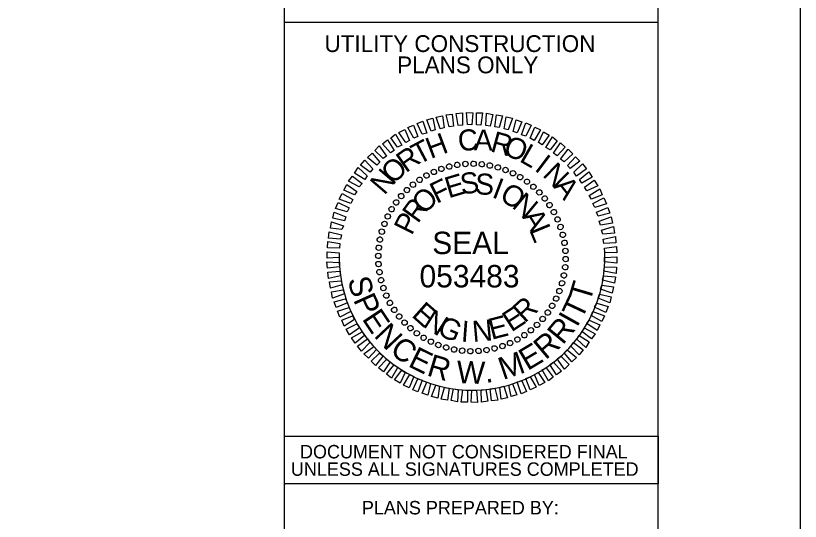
# Model space of a CAD drawing. Extents: x 2787886 to 2789612, y 1113277 to 1114394.
# Drawn here: x 2789401.8 to 2789611.8, y 1114118.8 to 1114254.2 of the extents above; entities that cross this region are included whole.
import ezdxf

# ---------------------------------------------------------------- set-up
doc = ezdxf.new("R2010")
doc.units = 0
for name, color, linetype in [('Scratch_Level_0', 7, 'Continuous'), ('Sheet PE Seal CELL', 7, 'Continuous'), ('Sheet Plan CELL', 7, 'Continuous'), ('Sheet_Data_Field_CELL', 7, 'Continuous'), ('Sheet_Plan_And_Profile_CELL', 7, 'Continuous'), ('Sheet_Plot_Border_Outside_CELL', 7, 'Continuous')]:
    doc.layers.add(name, color=color, linetype=linetype)

msp = doc.modelspace()

# ---------------------------------------------------------------- linework, layer by layer
at = {"layer": 'Scratch_Level_0'}
msp.add_arc((2789523.92, 1114189.47), 35.54, 180.0118, 2.0847, dxfattribs=at)
at = {"layer": 'Sheet PE Seal CELL'}
for p, q in [((2789515.68, 1114213.21), (2789515.68, 1114213.21)), ((2789517.78, 1114213.81), (2789517.78, 1114213.81)), ((2789519.98, 1114214.21), (2789519.98, 1114214.21)), ((2789522.13, 1114214.51), (2789522.13, 1114214.51)), ((2789524.33, 1114214.56), (2789524.33, 1114214.56)), ((2789526.53, 1114214.41), (2789526.53, 1114214.41)), ((2789528.68, 1114214.06), (2789528.68, 1114214.06)), ((2789530.78, 1114213.61), (2789530.78, 1114213.61)), ((2789532.88, 1114212.91), (2789532.88, 1114212.91)), ((2789511.73, 1114211.41), (2789511.73, 1114211.41)), ((2789513.68, 1114212.41), (2789513.68, 1114212.41)), ((2789534.88, 1114212.01), (2789534.88, 1114212.01)), ((2789536.83, 1114211.01), (2789536.83, 1114211.01)), ((2789508.08, 1114209.01), (2789508.08, 1114209.01)), ((2789509.83, 1114210.26), (2789509.83, 1114210.26)), ((2789538.63, 1114209.76), (2789538.63, 1114209.76)), ((2789540.38, 1114208.41), (2789540.38, 1114208.41)), ((2789506.43, 1114207.51), (2789506.43, 1114207.51)), ((2789541.93, 1114206.91), (2789541.93, 1114206.91)), ((2789503.58, 1114204.21), (2789503.58, 1114204.21)), ((2789504.93, 1114205.96), (2789504.93, 1114205.96)), ((2789543.43, 1114205.26), (2789543.43, 1114205.26)), ((2789502.33, 1114202.41), (2789502.33, 1114202.41)), ((2789544.68, 1114203.51), (2789544.68, 1114203.51)), ((2789501.33, 1114200.46), (2789501.33, 1114200.46)), ((2789545.83, 1114201.61), (2789545.83, 1114201.61)), ((2789500.43, 1114198.46), (2789500.43, 1114198.46)), ((2789546.83, 1114199.66), (2789546.83, 1114199.66)), ((2789499.73, 1114196.36), (2789499.73, 1114196.36)), ((2789547.63, 1114197.66), (2789547.63, 1114197.66)), ((2789499.28, 1114194.26), (2789499.28, 1114194.26)), ((2789548.23, 1114195.56), (2789548.23, 1114195.56)), ((2789498.93, 1114192.11), (2789498.93, 1114192.11)), ((2789548.63, 1114193.36), (2789548.63, 1114193.36)), ((2789498.78, 1114189.91), (2789498.78, 1114189.91)), ((2789523.88, 1114189.46), (2789523.88, 1114189.46)), ((2789548.93, 1114191.21), (2789548.93, 1114191.21)), ((2789498.83, 1114187.71), (2789498.83, 1114187.71)), ((2789548.98, 1114189.01), (2789548.98, 1114189.01)), ((2789499.13, 1114185.56), (2789499.13, 1114185.56)), ((2789548.83, 1114186.81), (2789548.83, 1114186.81)), ((2789499.53, 1114183.36), (2789499.53, 1114183.36)), ((2789548.48, 1114184.66), (2789548.48, 1114184.66)), ((2789500.13, 1114181.26), (2789500.13, 1114181.26)), ((2789548.03, 1114182.56), (2789548.03, 1114182.56)), ((2789500.93, 1114179.26), (2789500.93, 1114179.26)), ((2789547.33, 1114180.46), (2789547.33, 1114180.46)), ((2789501.93, 1114177.31), (2789501.93, 1114177.31)), ((2789546.43, 1114178.46), (2789546.43, 1114178.46)), ((2789503.08, 1114175.41), (2789503.08, 1114175.41)), ((2789545.43, 1114176.51), (2789545.43, 1114176.51)), ((2789504.33, 1114173.66), (2789504.33, 1114173.66)), ((2789542.83, 1114172.96), (2789542.83, 1114172.96)), ((2789544.18, 1114174.71), (2789544.18, 1114174.71)), ((2789505.83, 1114172.01), (2789505.83, 1114172.01)), ((2789541.33, 1114171.41), (2789541.33, 1114171.41)), ((2789507.38, 1114170.51), (2789507.38, 1114170.51)), ((2789509.13, 1114169.16), (2789509.13, 1114169.16)), ((2789537.93, 1114168.66), (2789537.93, 1114168.66)), ((2789539.68, 1114169.91), (2789539.68, 1114169.91)), ((2789510.93, 1114167.91), (2789510.93, 1114167.91)), ((2789512.88, 1114166.91), (2789512.88, 1114166.91)), ((2789534.08, 1114166.51), (2789534.08, 1114166.51)), ((2789536.03, 1114167.51), (2789536.03, 1114167.51)), ((2789514.88, 1114166.01), (2789514.88, 1114166.01)), ((2789516.98, 1114165.31), (2789516.98, 1114165.31)), ((2789519.08, 1114164.86), (2789519.08, 1114164.86)), ((2789521.23, 1114164.51), (2789521.23, 1114164.51)), ((2789523.43, 1114164.36), (2789523.43, 1114164.36)), ((2789525.63, 1114164.41), (2789525.63, 1114164.41)), ((2789527.78, 1114164.71), (2789527.78, 1114164.71)), ((2789529.98, 1114165.11), (2789529.98, 1114165.11)), ((2789532.08, 1114165.71), (2789532.08, 1114165.71))]:
    msp.add_line(p, q, dxfattribs=at)
for points in [[(2789515.38, 1114223.91), (2789514.33, 1114227.06), (2789516.03, 1114227.41), (2789516.43, 1114224.16)], [(2789517.78, 1114224.46), (2789516.98, 1114227.66), (2789518.63, 1114227.81), (2789518.98, 1114224.61)], [(2789520.18, 1114224.76), (2789519.63, 1114227.96), (2789521.33, 1114228.16), (2789521.38, 1114224.91)], [(2789522.68, 1114225.01), (2789522.43, 1114228.26), (2789524.08, 1114228.21), (2789523.88, 1114224.96)], [(2789525.08, 1114224.96), (2789525.08, 1114228.21), (2789526.73, 1114228.16), (2789526.28, 1114224.91)], [(2789527.58, 1114224.81), (2789527.78, 1114228.06), (2789529.43, 1114227.76), (2789528.78, 1114224.61)], [(2789529.98, 1114224.41), (2789530.43, 1114227.61), (2789532.08, 1114227.36), (2789531.18, 1114224.26)], [(2789510.53, 1114222.46), (2789509.23, 1114225.36), (2789510.73, 1114225.96), (2789511.78, 1114222.76)], [(2789512.98, 1114223.26), (2789511.83, 1114226.26), (2789513.38, 1114226.71), (2789514.03, 1114223.61)], [(2789532.53, 1114223.86), (2789533.03, 1114227.11), (2789534.73, 1114226.71), (2789533.58, 1114223.61)], [(2789534.93, 1114223.21), (2789535.68, 1114226.31), (2789537.23, 1114225.81), (2789535.98, 1114222.86)], [(2789537.18, 1114222.31), (2789538.33, 1114225.46), (2789539.73, 1114224.86), (2789538.33, 1114221.96)], [(2789506.18, 1114220.21), (2789504.33, 1114222.91), (2789505.88, 1114223.71), (2789507.13, 1114220.81)], [(2789508.33, 1114221.41), (2789506.73, 1114224.21), (2789508.28, 1114224.91), (2789509.43, 1114221.86)], [(2789539.43, 1114221.36), (2789540.68, 1114224.31), (2789542.23, 1114223.61), (2789540.53, 1114220.81)], [(2789541.73, 1114220.21), (2789543.08, 1114223.06), (2789544.58, 1114222.21), (2789542.68, 1114219.61)], [(2789503.98, 1114218.96), (2789502.13, 1114221.51), (2789503.43, 1114222.46), (2789505.08, 1114219.56)], [(2789543.68, 1114218.86), (2789545.43, 1114221.76), (2789546.73, 1114220.71), (2789544.78, 1114218.26)], [(2789500.08, 1114215.91), (2789497.88, 1114218.11), (2789499.08, 1114219.31), (2789501.03, 1114216.61)], [(2789502.08, 1114217.46), (2789499.93, 1114219.86), (2789501.28, 1114220.91), (2789503.03, 1114218.11)], [(2789545.73, 1114217.36), (2789547.58, 1114220.11), (2789548.88, 1114219.01), (2789546.68, 1114216.66)], [(2789498.43, 1114214.16), (2789495.88, 1114216.21), (2789497.13, 1114217.36), (2789499.23, 1114214.96)], [(2789547.63, 1114215.81), (2789549.68, 1114218.41), (2789550.88, 1114217.21), (2789548.58, 1114215.06)], [(2789496.68, 1114212.26), (2789494.08, 1114214.21), (2789495.18, 1114215.51), (2789497.38, 1114213.16)], [(2789549.43, 1114214.06), (2789551.58, 1114216.41), (2789552.78, 1114215.21), (2789550.18, 1114213.26)], [(2789495.18, 1114210.36), (2789492.48, 1114212.06), (2789493.43, 1114213.51), (2789495.83, 1114211.31)], [(2789551.18, 1114212.26), (2789553.48, 1114214.51), (2789554.53, 1114213.16), (2789551.88, 1114211.26)], [(2789493.68, 1114208.36), (2789490.88, 1114209.86), (2789491.88, 1114211.26), (2789494.48, 1114209.26)], [(2789552.68, 1114210.31), (2789555.13, 1114212.41), (2789556.08, 1114210.96), (2789553.28, 1114209.36)], [(2789492.48, 1114206.21), (2789489.63, 1114207.46), (2789490.38, 1114209.01), (2789493.08, 1114207.16)], [(2789553.98, 1114208.26), (2789556.63, 1114210.16), (2789557.58, 1114208.66), (2789554.68, 1114207.26)], [(2789491.48, 1114203.91), (2789488.38, 1114205.06), (2789489.13, 1114206.61), (2789491.98, 1114205.01)], [(2789555.28, 1114206.06), (2789558.08, 1114207.81), (2789558.73, 1114206.26), (2789555.88, 1114205.11)], [(2789490.48, 1114201.71), (2789487.38, 1114202.61), (2789488.03, 1114204.16), (2789491.03, 1114202.76)], [(2789556.28, 1114203.91), (2789559.23, 1114205.41), (2789559.88, 1114203.81), (2789556.78, 1114202.81)], [(2789557.18, 1114201.56), (2789560.23, 1114202.86), (2789560.78, 1114201.31), (2789557.68, 1114200.51)], [(2789489.73, 1114199.31), (2789486.63, 1114199.96), (2789486.98, 1114201.61), (2789490.13, 1114200.36)], [(2789557.98, 1114199.16), (2789561.18, 1114200.31), (2789561.48, 1114198.66), (2789558.33, 1114198.11)], [(2789489.08, 1114196.91), (2789485.98, 1114197.31), (2789486.33, 1114199.01), (2789489.48, 1114197.96)], [(2789488.68, 1114194.36), (2789485.48, 1114194.66), (2789485.68, 1114196.36), (2789488.93, 1114195.56)], [(2789558.58, 1114196.76), (2789561.73, 1114197.71), (2789562.03, 1114196.01), (2789558.88, 1114195.71)], [(2789488.43, 1114191.96), (2789485.18, 1114192.06), (2789485.28, 1114193.71), (2789488.53, 1114193.16)], [(2789559.03, 1114194.36), (2789562.28, 1114195.06), (2789562.43, 1114193.36), (2789559.23, 1114193.16)], [(2789559.33, 1114191.96), (2789562.58, 1114192.36), (2789562.68, 1114190.66), (2789559.43, 1114190.76)], [(2789488.38, 1114189.46), (2789485.13, 1114189.31), (2789485.13, 1114191.01), (2789488.38, 1114190.66)], [(2789559.38, 1114189.46), (2789562.63, 1114189.61), (2789562.63, 1114187.91), (2789559.38, 1114188.26)], [(2789488.43, 1114186.96), (2789485.18, 1114186.56), (2789485.08, 1114188.26), (2789488.33, 1114188.16)], [(2789488.73, 1114184.56), (2789485.48, 1114183.86), (2789485.33, 1114185.56), (2789488.53, 1114185.76)], [(2789559.33, 1114186.96), (2789562.58, 1114186.86), (2789562.48, 1114185.21), (2789559.23, 1114185.76)], [(2789489.18, 1114182.16), (2789486.03, 1114181.21), (2789485.73, 1114182.91), (2789488.88, 1114183.21)], [(2789559.08, 1114184.56), (2789562.28, 1114184.26), (2789562.08, 1114182.56), (2789558.83, 1114183.36)], [(2789558.68, 1114182.01), (2789561.78, 1114181.61), (2789561.43, 1114179.91), (2789558.28, 1114180.96)], [(2789489.78, 1114179.76), (2789486.58, 1114178.61), (2789486.28, 1114180.26), (2789489.43, 1114180.81)], [(2789558.03, 1114179.61), (2789561.13, 1114178.96), (2789560.78, 1114177.31), (2789557.63, 1114178.56)], [(2789490.58, 1114177.36), (2789487.53, 1114176.06), (2789486.98, 1114177.61), (2789490.08, 1114178.41)], [(2789557.28, 1114177.21), (2789560.38, 1114176.31), (2789559.73, 1114174.76), (2789556.73, 1114176.16)], [(2789491.48, 1114175.01), (2789488.53, 1114173.51), (2789487.88, 1114175.11), (2789490.98, 1114176.11)], [(2789556.28, 1114175.01), (2789559.38, 1114173.86), (2789558.63, 1114172.31), (2789555.78, 1114173.91)], [(2789492.48, 1114172.86), (2789489.68, 1114171.11), (2789489.03, 1114172.66), (2789491.88, 1114173.81)], [(2789555.28, 1114172.71), (2789558.13, 1114171.46), (2789557.38, 1114169.91), (2789554.68, 1114171.76)], [(2789493.78, 1114170.66), (2789491.13, 1114168.76), (2789490.18, 1114170.26), (2789493.08, 1114171.66)], [(2789554.08, 1114170.56), (2789556.88, 1114169.06), (2789555.88, 1114167.66), (2789553.28, 1114169.66)], [(2789495.08, 1114168.61), (2789492.63, 1114166.51), (2789491.68, 1114167.96), (2789494.48, 1114169.56)], [(2789552.58, 1114168.56), (2789555.28, 1114166.86), (2789554.33, 1114165.41), (2789551.93, 1114167.61)], [(2789496.58, 1114166.66), (2789494.28, 1114164.41), (2789493.23, 1114165.76), (2789495.88, 1114167.66)], [(2789551.08, 1114166.66), (2789553.68, 1114164.71), (2789552.58, 1114163.41), (2789550.38, 1114165.76)], [(2789498.33, 1114164.86), (2789496.18, 1114162.51), (2789494.98, 1114163.71), (2789497.58, 1114165.66)], [(2789549.33, 1114164.76), (2789551.88, 1114162.71), (2789550.63, 1114161.56), (2789548.53, 1114163.96)], [(2789500.13, 1114163.11), (2789498.08, 1114160.51), (2789496.88, 1114161.71), (2789499.18, 1114163.86)], [(2789502.03, 1114161.56), (2789500.18, 1114158.81), (2789498.88, 1114159.91), (2789501.08, 1114162.26)], [(2789547.68, 1114163.01), (2789549.88, 1114160.81), (2789548.68, 1114159.61), (2789546.73, 1114162.31)], [(2789504.08, 1114160.06), (2789502.33, 1114157.16), (2789501.03, 1114158.21), (2789502.98, 1114160.66)], [(2789545.68, 1114161.46), (2789547.83, 1114159.06), (2789546.48, 1114158.01), (2789544.73, 1114160.81)], [(2789506.03, 1114158.71), (2789504.68, 1114155.86), (2789503.18, 1114156.71), (2789505.08, 1114159.31)], [(2789508.33, 1114157.56), (2789507.08, 1114154.61), (2789505.53, 1114155.31), (2789507.23, 1114158.11)], [(2789541.58, 1114158.71), (2789543.43, 1114156.01), (2789541.88, 1114155.21), (2789540.63, 1114158.11)], [(2789543.78, 1114159.96), (2789545.63, 1114157.41), (2789544.33, 1114156.46), (2789542.68, 1114159.36)], [(2789510.58, 1114156.61), (2789509.43, 1114153.46), (2789508.03, 1114154.06), (2789509.43, 1114156.96)], [(2789512.83, 1114155.71), (2789512.08, 1114152.61), (2789510.53, 1114153.11), (2789511.78, 1114156.06)], [(2789537.23, 1114156.46), (2789538.53, 1114153.56), (2789537.03, 1114152.96), (2789535.98, 1114156.16)], [(2789539.43, 1114157.51), (2789541.03, 1114154.71), (2789539.48, 1114154.01), (2789538.33, 1114157.06)], [(2789515.23, 1114155.06), (2789514.73, 1114151.81), (2789513.03, 1114152.21), (2789514.18, 1114155.31)], [(2789517.78, 1114154.51), (2789517.33, 1114151.31), (2789515.68, 1114151.56), (2789516.58, 1114154.66)], [(2789520.18, 1114154.11), (2789519.98, 1114150.86), (2789518.33, 1114151.16), (2789518.98, 1114154.31)], [(2789522.68, 1114153.96), (2789522.68, 1114150.71), (2789521.03, 1114150.76), (2789521.48, 1114154.01)], [(2789525.08, 1114153.91), (2789525.33, 1114150.66), (2789523.68, 1114150.71), (2789523.88, 1114153.96)], [(2789527.58, 1114154.16), (2789528.13, 1114150.96), (2789526.43, 1114150.76), (2789526.38, 1114154.01)], [(2789529.98, 1114154.46), (2789530.78, 1114151.26), (2789529.13, 1114151.11), (2789528.78, 1114154.31)], [(2789532.38, 1114155.01), (2789533.43, 1114151.86), (2789531.73, 1114151.51), (2789531.33, 1114154.76)], [(2789534.78, 1114155.66), (2789535.93, 1114152.66), (2789534.38, 1114152.21), (2789533.73, 1114155.31)]]:
    msp.add_lwpolyline(points, close=True, dxfattribs=at)
for centre, major_axis in [((2789519.96, 1114214.23), (-0.113, 0.711)), ((2789522.13, 1114214.48), (-0.05, 0.718)), ((2789524.32, 1114214.53), (0.013, 0.72)), ((2789526.5, 1114214.4), (0.075, 0.716)), ((2789528.67, 1114214.08), (0.137, 0.707)), ((2789513.68, 1114212.37), (-0.293, 0.658)), ((2789515.71, 1114213.17), (-0.234, 0.681)), ((2789517.81, 1114213.79), (-0.174, 0.699)), ((2789530.79, 1114213.57), (0.198, 0.692)), ((2789532.87, 1114212.87), (0.258, 0.672)), ((2789534.87, 1114212), (0.316, 0.647)), ((2789509.86, 1114210.25), (-0.403, 0.597)), ((2789511.72, 1114211.39), (-0.349, 0.63)), ((2789536.8, 1114210.96), (0.371, 0.617)), ((2789538.62, 1114209.75), (0.423, 0.582)), ((2789508.1, 1114208.95), (-0.453, 0.56)), ((2789540.33, 1114208.39), (0.472, 0.543)), ((2789504.95, 1114205.91), (-0.543, 0.472)), ((2789506.46, 1114207.5), (-0.5, 0.518)), ((2789541.92, 1114206.88), (0.518, 0.5)), ((2789503.59, 1114204.2), (-0.582, 0.423)), ((2789543.37, 1114205.24), (0.56, 0.453)), ((2789544.67, 1114203.48), (0.597, 0.403)), ((2789502.38, 1114202.38), (-0.617, 0.371)), ((2789545.82, 1114201.62), (0.63, 0.349)), ((2789501.34, 1114200.45), (-0.647, 0.316)), ((2789546.79, 1114199.66), (0.658, 0.293)), ((2789500.47, 1114198.45), (-0.672, 0.258)), ((2789547.59, 1114197.62), (0.681, 0.234)), ((2789499.77, 1114196.37), (-0.692, 0.198)), ((2789548.22, 1114195.53), (0.699, 0.174)), ((2789499.26, 1114194.24), (-0.707, 0.137)), ((2789548.65, 1114193.38), (0.711, 0.113)), ((2789498.94, 1114192.08), (-0.716, 0.075)), ((2789548.9, 1114191.21), (0.718, 0.05)), ((2789498.8, 1114189.9), (-0.72, 0.013)), ((2789548.96, 1114189.02), (0.72, -0.013)), ((2789498.86, 1114187.71), (-0.718, -0.05)), ((2789548.82, 1114186.84), (0.716, -0.075)), ((2789499.11, 1114185.54), (-0.711, -0.113)), ((2789548.5, 1114184.67), (0.707, -0.137)), ((2789499.55, 1114183.39), (-0.699, -0.174)), ((2789547.99, 1114182.55), (0.692, -0.198)), ((2789500.17, 1114181.29), (-0.681, -0.234)), ((2789547.29, 1114180.47), (0.672, -0.258)), ((2789500.97, 1114179.26), (-0.658, -0.293)), ((2789546.42, 1114178.46), (0.647, -0.316)), ((2789501.94, 1114177.3), (-0.63, -0.349)), ((2789545.38, 1114176.54), (0.617, -0.371)), ((2789503.09, 1114175.43), (-0.597, -0.403)), ((2789544.17, 1114174.72), (0.582, -0.423)), ((2789504.39, 1114173.68), (-0.56, -0.453)), ((2789505.84, 1114172.04), (-0.518, -0.5)), ((2789542.81, 1114173), (0.543, -0.472)), ((2789507.43, 1114170.53), (-0.472, -0.543)), ((2789539.66, 1114169.97), (0.453, -0.56)), ((2789541.3, 1114171.42), (0.5, -0.518)), ((2789509.14, 1114169.17), (-0.423, -0.582)), ((2789510.96, 1114167.96), (-0.371, -0.617)), ((2789537.9, 1114168.67), (0.403, -0.597)), ((2789512.89, 1114166.92), (-0.316, -0.647)), ((2789514.89, 1114166.04), (-0.258, -0.672)), ((2789532.05, 1114165.75), (0.234, -0.681)), ((2789534.08, 1114166.55), (0.293, -0.658)), ((2789536.04, 1114167.52), (0.349, -0.63)), ((2789516.97, 1114165.35), (-0.198, -0.692)), ((2789519.09, 1114164.84), (-0.137, -0.707)), ((2789521.26, 1114164.52), (-0.075, -0.716)), ((2789523.44, 1114164.38), (-0.013, -0.72)), ((2789525.63, 1114164.44), (0.05, -0.718)), ((2789527.8, 1114164.69), (0.113, -0.711)), ((2789529.95, 1114165.12), (0.174, -0.699))]:
    msp.add_ellipse(centre, major_axis=major_axis, ratio=0.999708, dxfattribs=at)
at = {"layer": 'Sheet Plan CELL'}
msp.add_line((2789573.71, 1114128.86), (2789473.69, 1114128.86), dxfattribs=at)
at = {"layer": 'Sheet_Data_Field_CELL'}
msp.add_lwpolyline([(2789473.71, 1114141.6), (2789573.69, 1114141.6), (2789573.69, 1114128.87), (2789473.71, 1114128.87)], close=True, dxfattribs=at)
at = {"layer": 'Sheet_Plan_And_Profile_CELL'}
for p, q in [((2789473.69, 1113308.25), (2789473.72, 1114363.23)), ((2789573.69, 1113308.25), (2789573.71, 1114363.23)), ((2789573.74, 1114252.36), (2789473.74, 1114252.36))]:
    msp.add_line(p, q, dxfattribs=at)
for points in [[(2789473.69, 1114141.6), (2789573.69, 1114141.6), (2789573.69, 1114128.86), (2789473.69, 1114128.86)], [(2789473.69, 1114128.86), (2789473.85, 1114128.86), (2789473.85, 1114128.84), (2789473.69, 1114128.84)]]:
    msp.add_lwpolyline(points, close=True, dxfattribs=at)
at = {"layer": 'Sheet_Plot_Border_Outside_CELL'}
msp.add_lwpolyline([(2787885.62, 1114394.2), (2789611.78, 1114394.2), (2789611.78, 1113277.27), (2787885.62, 1113277.27)], close=True, dxfattribs=at)

# ---------------------------------------------------------------- texts
at = {"layer": 'Sheet PE Seal CELL'}
for s, height, rotation, p in [('C', 5.64, 6.2199, (2789520.43, 1114217.81)), ('A', 5.64, 359.0203, (2789524.38, 1114218.11)), ('R', 5.64, 344.6211, (2789528.58, 1114217.91)), ('T', 5.64, 27.8198, (2789509.58, 1114214.16)), ('H', 5.64, 20.6195, (2789512.83, 1114215.81)), ('O', 5.64, 337.4212, (2789531.93, 1114217.16)), ('L', 5.64, 330.2209, (2789536.33, 1114215.31)), ('R', 5.64, 35.0205, (2789506.18, 1114211.96)), ('I', 5.64, 323.0201, (2789540.38, 1114212.91)), ('O', 5.64, 42.2217, (2789502.73, 1114208.86)), ('N', 5.64, 315.8189, (2789542.53, 1114211.36)), ('N', 5.64, 49.4235, (2789500.43, 1114205.96)), ('F', 5.64, 25.967, (2789514.43, 1114203.76)), ('E', 5.64, 16.6111, (2789517.63, 1114205.26)), ('S', 5.64, 7.2556, (2789521.08, 1114206.31)), ('S', 5.64, 357.9004, (2789524.68, 1114206.36)), ('I', 5.64, 339.1896, (2789528.98, 1114205.66)), ('O', 5.64, 329.8335, (2789530.98, 1114204.96)), ('A', 5.64, 308.6172, (2789545.48, 1114208.41)), ('O', 5.64, 44.6812, (2789511.13, 1114200.81)), ('N', 5.64, 320.4766, (2789534.33, 1114202.96)), ('R', 5.64, 54.0397, (2789509.38, 1114198.36)), ('P', 5.64, 63.3989, (2789507.78, 1114195.16)), ('A', 5.64, 301.7603, (2789537.18, 1114200.36)), ('L', 5.64, 292.4009, (2789539.13, 1114196.91)), ('SEAL', 5.998, 360, (2789513.25, 1114190.36)), ('S', 6, 284.7638, (2789490.58, 1114183.57)), ('T', 6, 73.4708, (2789555.46, 1114177.19)), ('P', 6, 294.2618, (2789492.01, 1114178.15)), ('T', 6, 64.7726, (2789553.24, 1114172.56)), ('E', 5.64, 318.2769, (2789507.48, 1114173.81)), ('R', 5.64, 42.4814, (2789537.98, 1114171.71)), ('E', 6, 303.7599, (2789494.31, 1114173.04)), ('N', 5.64, 327.634, (2789510.48, 1114171.11)), ('E', 5.64, 33.1241, (2789534.43, 1114169.36)), ('I', 6, 60.8196, (2789552.01, 1114170.58)), ('G', 5.64, 336.9902, (2789514.28, 1114168.86)), ('N', 5.64, 5.0564, (2789524.18, 1114166.81)), ('E', 5.64, 14.4118, (2789529.13, 1114167.41)), ('R', 6, 50.5372, (2789548.19, 1114165.86)), ('N', 6, 313.2579, (2789497.43, 1114168.38)), ('I', 5.64, 355.7012, (2789520.83, 1114166.96)), ('R', 6, 40.2548, (2789543.58, 1114161.91)), ('C', 6, 323.5403, (2789501.62, 1114163.99)), ('E', 6, 30.7567, (2789538.77, 1114159.04)), ('E', 6, 333.8228, (2789506.52, 1114160.42)), ('M', 6, 18.8977, (2789532.2, 1114156.64)), ('R', 6, 343.3208, (2789511.56, 1114157.95)), ('W', 6, 357.5563, (2789519.68, 1114155.88)), ('.', 6, 10.9918, (2789527.6, 1114155.81))]:
    msp.add_text(s, height=height, rotation=rotation, dxfattribs=at).set_placement(p)
msp.add_text('053483', height=5.998, dxfattribs=at).set_placement((2789509.85, 1114181.45))
at = {"layer": 'Sheet Plan CELL'}
msp.add_text('PLANS PREPARED BY:', height=3.6008, rotation=0, dxfattribs=at).set_placement((2789494.42, 1114120.69))
at = {"layer": 'Sheet_Data_Field_CELL'}
for s, p in [('DOCUMENT NOT CONSIDERED FINAL', (2789477.86, 1114135.68)), ('UNLESS ALL SIGNATURES COMPLETED', (2789475.42, 1114131.02))]:
    msp.add_text(s, height=3.5992, rotation=0, dxfattribs=at).set_placement(p)
at = {"layer": 'Sheet_Plan_And_Profile_CELL'}
for s, height, p in [('UTILITY CONSTRUCTION', 4.5, (2789484.4, 1114244.45)), ('PLANS ONLY', 4.5, (2789503.86, 1114238.76)), ('DOCUMENT NOT CONSIDERED FINAL', 0.006, (2789473.69, 1114128.85)), ('UNLESS ALL SIGNATURES COMPLETED', 0.006, (2789473.69, 1114128.84))]:
    msp.add_text(s, height=height, rotation=0, dxfattribs=at).set_placement(p)

doc.saveas('drawing.dxf')
